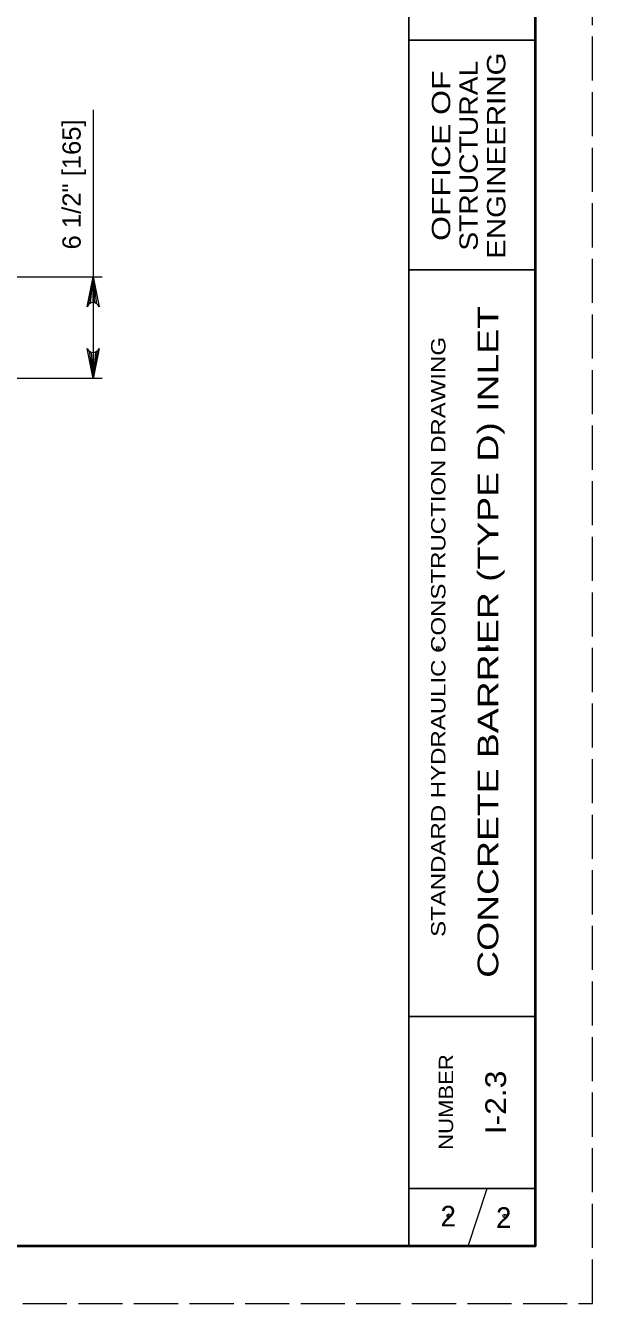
# Model space of a CAD drawing. Extents: x -1431.2 to -1397.2, y -1045.1 to -1001.1.
# Drawn here: x -1402.18 to -1397.25, y -1045.08 to -1033.95 of the extents above; entities that cross this region are included whole.
import ezdxf
from ezdxf.enums import TextEntityAlignment as Align

# ---------------------------------------------------------------- set-up
doc = ezdxf.new("R2010")
doc.units = 0
doc.header["$LTSCALE"] = 0.064
doc.header["$PDMODE"] = 32
doc.header["$PDSIZE"] = 0.032
doc.linetypes.add('LONG_DASHED', pattern=[7.5, 6, -1.5])
doc.layers.add('1', color=7, linetype='Continuous', lineweight=13)

msp = doc.modelspace()

# ---------------------------------------------------------------- linework, layer by layer
at = {"layer": '1', "lineweight": 25}
for p, q in [((-1398.84575, -1044.57983), (-1398.84575, -1023.57983)), ((-1397.74575, -1023.57983), (-1397.74575, -1044.57983)), ((-1397.74575, -1034.07983), (-1398.84575, -1034.07983)), ((-1397.74575, -1036.07983), (-1398.84575, -1036.07983)), ((-1397.74575, -1042.57983), (-1398.84575, -1042.57983)), ((-1397.74575, -1044.07983), (-1398.84575, -1044.07983))]:
    msp.add_line(p, q, dxfattribs=at)
at = {"layer": '1'}
for p, q in [((-1401.594, -1034.68475), (-1401.594, -1037.0245)), ((-1403.97425, -1036.13875), (-1401.51458, -1036.13875)), ((-1401.63058, -1036.37833), (-1401.594, -1036.13875)), ((-1401.61525, -1036.36925), (-1401.594, -1036.13875)), ((-1401.594, -1036.36508), (-1401.594, -1036.13875)), ((-1401.57725, -1036.3675), (-1401.594, -1036.13875)), ((-1401.56083, -1036.3755), (-1401.594, -1036.13875)), ((-1401.62708, -1036.78775), (-1401.594, -1037.0245)), ((-1401.61075, -1036.79575), (-1401.594, -1037.0245)), ((-1401.55733, -1036.78492), (-1401.594, -1037.0245)), ((-1401.57275, -1036.794), (-1401.594, -1037.0245)), ((-1401.594, -1036.79817), (-1401.594, -1037.0245)), ((-1401.51458, -1037.0245), (-1403.67092, -1037.0245)), ((-1402.13467, -1037.0245), (-1402.13467, -1037.02617)), ((-1398.32908, -1044.57983), (-1398.16242, -1044.07983))]:
    msp.add_line(p, q, dxfattribs=at)
at = {"layer": '1', "linetype": 'LONG_DASHED'}
msp.add_lwpolyline([(-1431.24575, -1045.07983), (-1397.24575, -1045.07983), (-1397.24575, -1023.07983), (-1431.24575, -1023.07983)], close=True, dxfattribs=at)
at = {"layer": '1', "lineweight": 25}
msp.add_lwpolyline([(-1397.74575, -1044.57983), (-1429.24575, -1044.57983), (-1429.24575, -1023.57983)], dxfattribs=at)
at = {"layer": '1', "lineweight": 40}
msp.add_lwpolyline([(-1429.24575, -1023.57983), (-1397.74575, -1023.57983), (-1397.74575, -1044.57983), (-1429.24575, -1044.57983)], close=True, dxfattribs=at)
at = {"layer": '1'}
for points in [[(-1401.64625, -1036.40025), (-1401.594, -1036.13875), (-1401.54167, -1036.40025)], [(-1401.54167, -1036.76292), (-1401.594, -1037.0245), (-1401.64625, -1036.76292)]]:
    msp.add_lwpolyline(points, dxfattribs=at)
for centre, start, end in [((-1401.59393, -1036.42139), 22.08782, 157.91395), ((-1401.59404, -1036.74184), 202.08782, 337.91395)]:
    msp.add_arc(centre, 0.05644, start, end, dxfattribs=at)
for p in [(-1398.58833, -1039.37383), (-1398.1555, -1039.3665), (-1398.49767, -1044.31608), (-1398.00925, -1044.31708)]:
    msp.add_point(p, dxfattribs=at)

# ---------------------------------------------------------------- texts
for s, height, width, p in [('ENGINEERING', 0.16, 1.2, (-1398.004, -1035.08529)), ('STRUCTURAL', 0.16, 1.15, (-1398.244, -1035.08537)), ('OFFICE OF', 0.16, 1.3, (-1398.484, -1035.08537)), ('6 1/2" [165]', 0.1588, 1.05, (-1401.70208, -1035.33546)), ('CONCRETE BARRIER (TYPE D) INLET', 0.18, 1.35, (-1398.0655, -1039.31967)), ('STANDARD HYDRAULIC CONSTRUCTION DRAWING', 0.125, 1.25, (-1398.52583, -1039.27579)), ('NUMBER', 0.125, 1.15, (-1398.45875, -1043.32575)), ('I-2.3', 0.18, 1.15, (-1397.9985, -1043.32946))]:
    msp.add_text(s, height=height, rotation=90, dxfattribs=dict(at, width=width)).set_placement(p, align=Align.CENTER)
for p in [(-1398.50129, -1044.40975), (-1398.01846, -1044.42233)]:
    msp.add_text('2', height=0.18, dxfattribs=at).set_placement(p, align=Align.CENTER)

doc.saveas('drawing.dxf')
